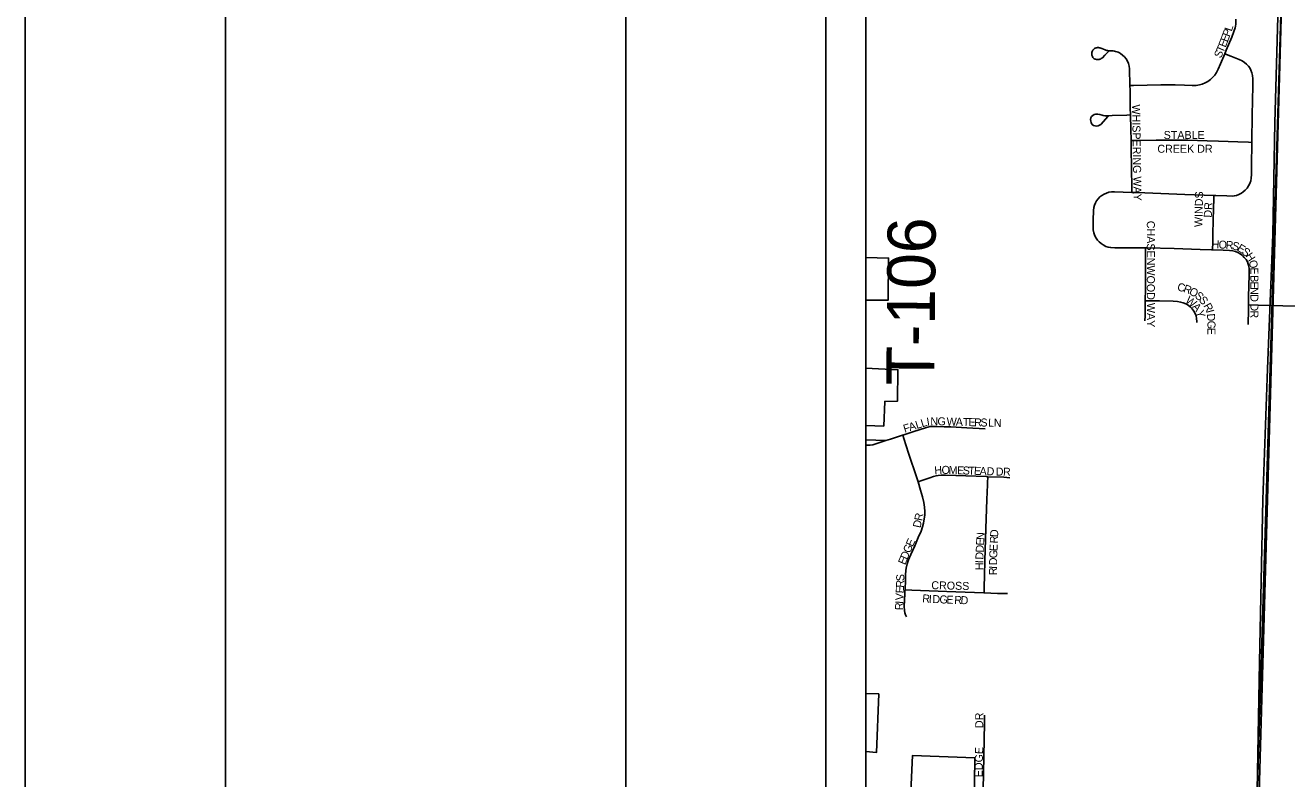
# Model space of a CAD drawing. Extents: x -5.6 to 34, y 0 to 22.
# Drawn here: x 0 to 3.152, y 14.869 to 16.752 of the extents above; entities that cross this region are included whole.
import ezdxf

# ---------------------------------------------------------------- set-up
doc = ezdxf.new("R2010")
doc.units = 0
for name, color, linetype in [('GM_X_City_Street', 7, 'Continuous'), ('GM_X_City_Street_Text', 7, 'Continuous'), ('GM_X_Corporation', 7, 'Continuous'), ('GM_X_Minor_River', 7, 'Continuous'), ('GM_X_Section', 7, 'Continuous'), ('GM_X_Township', 7, 'Continuous'), ('GM_X_Township_Road_Text', 7, 'Continuous'), ('SH_Border', 7, 'Continuous'), ('SH_Cut_Line', 7, 'Continuous'), ('SH_Data', 7, 'Continuous')]:
    doc.layers.add(name, color=color, linetype=linetype)

msp = doc.modelspace()

# ---------------------------------------------------------------- linework, layer by layer
at = {"layer": 'GM_X_City_Street'}
msp.add_line((2.1, 15.7156), (2.15, 15.7141), dxfattribs=at)
for points in [[(2.9966, 16.6798), (3.0005, 16.6891), (3.014, 16.7221), (3.0195, 16.7357), (3.0223, 16.7448), (3.0233, 16.7491), (3.0242, 16.7546), (3.0246, 16.7584), (3.0246, 16.7617), (3.0242, 16.7668)], [(2.7597, 16.6009), (2.7586, 16.6428), (2.7577, 16.6493), (2.7559, 16.6556), (2.7533, 16.6616), (2.7501, 16.6674), (2.7461, 16.6726), (2.7413, 16.6771), (2.736, 16.6809), (2.7333, 16.6824), (2.7302, 16.684), (2.7272, 16.6852), (2.724, 16.6862), (2.7209, 16.687), (2.7176, 16.6876), (2.7097, 16.6879), (2.706, 16.688), (2.7036, 16.6882), (2.7018, 16.6885), (2.6999, 16.689), (2.6977, 16.6899), (2.6896, 16.6932), (2.6847, 16.695), (2.6827, 16.6954), (2.6808, 16.6957), (2.679, 16.6957), (2.677, 16.6955), (2.675, 16.695), (2.6732, 16.6942), (2.6714, 16.6931), (2.6699, 16.692), (2.6684, 16.6907), (2.6671, 16.6894), (2.6661, 16.6878), (2.665, 16.6859), (2.6644, 16.6838), (2.6643, 16.6816), (2.6643, 16.6796), (2.6646, 16.6769), (2.6651, 16.6752), (2.6659, 16.6732), (2.6673, 16.671), (2.6691, 16.6691), (2.6708, 16.668), (2.6725, 16.6671), (2.6741, 16.6665), (2.6763, 16.666), (2.6783, 16.6657), (2.6802, 16.6659), (2.6825, 16.6661), (2.6845, 16.6666), (2.6861, 16.6671), (2.6881, 16.6682), (2.6894, 16.6691), (2.6909, 16.6704), (2.6971, 16.6767), (2.7078, 16.6872)], [(2.7597, 16.6009), (2.7689, 16.6012), (2.8024, 16.602), (2.8369, 16.6026), (2.8731, 16.6024), (2.8963, 16.6015), (2.9148, 16.6009), (2.9255, 16.6012), (2.9335, 16.6023), (2.9401, 16.6042), (2.9476, 16.6073), (2.9547, 16.6112), (2.9613, 16.616), (2.9662, 16.6206), (2.9715, 16.6268), (2.976, 16.6335), (2.9804, 16.6418), (2.9862, 16.6552), (2.9966, 16.6798)], [(3.0643, 16.459), (3.0652, 16.5299), (3.0659, 16.5601), (3.0668, 16.6034), (3.0668, 16.618), (3.066, 16.6261), (3.0645, 16.6327), (3.0621, 16.6391), (3.0589, 16.6451), (3.0556, 16.6496), (3.0509, 16.6545), (3.0456, 16.6587), (3.0398, 16.6623), (3.0325, 16.6658), (3.0117, 16.6739), (2.9966, 16.6798)], [(2.761, 16.5275), (2.7606, 16.5456), (2.76, 16.589), (2.7597, 16.6009)], [(2.7057, 16.524), (2.6873, 16.5039), (2.6841, 16.5017), (2.6804, 16.5003), (2.6765, 16.4998), (2.6726, 16.5002), (2.6689, 16.5015), (2.6657, 16.5039), (2.6641, 16.5059), (2.6629, 16.5083), (2.6618, 16.5121), (2.6616, 16.516), (2.6623, 16.5199), (2.6641, 16.5234), (2.6669, 16.5262), (2.6702, 16.5282), (2.674, 16.5295), (2.6793, 16.5298), (2.6844, 16.5287), (2.6903, 16.5268), (2.6932, 16.5261), (2.6974, 16.5255), (2.7022, 16.5253), (2.7156, 16.5259), (2.7518, 16.5272), (2.761, 16.5275)], [(2.7625, 16.4633), (2.7618, 16.4918), (2.761, 16.5275)], [(2.7625, 16.4633), (2.7812, 16.4637), (2.8252, 16.4645), (2.873, 16.4648), (2.9043, 16.4645), (2.9527, 16.4631), (2.9809, 16.4622), (3.0296, 16.4602), (3.056, 16.4593), (3.0643, 16.459)], [(2.7643, 16.3338), (2.7642, 16.346), (2.7637, 16.3946), (2.763, 16.4445), (2.7625, 16.4633)], [(2.9696, 16.3265), (2.9741, 16.3263), (3.0016, 16.3251), (3.0149, 16.3248), (3.0204, 16.3253), (3.0257, 16.3265), (3.0321, 16.3288), (3.0382, 16.3319), (3.0428, 16.335), (3.0478, 16.3395), (3.0524, 16.3446), (3.0562, 16.3503), (3.0592, 16.3564), (3.0614, 16.3629), (3.0628, 16.3695), (3.0636, 16.3789), (3.0636, 16.4065), (3.0642, 16.4525), (3.0643, 16.459)], [(2.7988, 16.1951), (2.7576, 16.1953), (2.7222, 16.1956), (2.7119, 16.1961), (2.7057, 16.1972), (2.6998, 16.1992), (2.6929, 16.2026), (2.6876, 16.206), (2.6828, 16.2101), (2.6786, 16.2148), (2.6751, 16.22), (2.6723, 16.2256), (2.6697, 16.2328), (2.6682, 16.2402), (2.6676, 16.2479), (2.6677, 16.2649), (2.6685, 16.2884), (2.6694, 16.2959), (2.6709, 16.3021), (2.6733, 16.3078), (2.6765, 16.3133), (2.6804, 16.3182), (2.6849, 16.3227), (2.6898, 16.3266), (2.6952, 16.3299), (2.701, 16.3324), (2.707, 16.3342), (2.7133, 16.3352), (2.7209, 16.3356), (2.7643, 16.3338)], [(2.7643, 16.3338), (2.7773, 16.3333), (2.8573, 16.3304), (2.8967, 16.329), (2.9696, 16.3265)], [(2.9658, 16.1904), (2.9666, 16.2094), (2.9671, 16.2287), (2.968, 16.2655), (2.9694, 16.3185), (2.9696, 16.3265)], [(2.7981, 16.0635), (2.7986, 16.0927), (2.7988, 16.1764), (2.7988, 16.1951)], [(2.9658, 16.1904), (2.9638, 16.1905), (2.9349, 16.1917), (2.8706, 16.1935), (2.801, 16.1951), (2.7988, 16.1951)], [(3.0561, 16.0534), (3.0562, 16.0733), (3.0574, 16.1284), (3.0575, 16.143), (3.0566, 16.1498), (3.0552, 16.1551), (3.0532, 16.1602), (3.0497, 16.1661), (3.0455, 16.1715), (3.0408, 16.1764), (3.0354, 16.1806), (3.0295, 16.184), (3.0231, 16.1865), (3.0165, 16.1881), (3.0084, 16.189), (2.9926, 16.1894), (2.9658, 16.1904)], [(2.797, 16.0128), (2.7974, 16.0259), (2.7981, 16.0635)], [(2.7981, 16.0635), (2.8034, 16.0634), (2.8135, 16.0632), (2.8338, 16.0627), (2.8678, 16.062), (2.8784, 16.0613), (2.8863, 16.06), (2.8929, 16.0583), (2.8991, 16.0557), (2.905, 16.0522), (2.9104, 16.048), (2.9151, 16.0431), (2.9192, 16.0376), (2.9224, 16.0317), (2.9248, 16.0253), (2.9263, 16.0186), (2.9268, 16.0118), (2.9267, 16.0091)], [(3.0552, 16.0037), (3.056, 16.0418), (3.0561, 16.0534)], [(3.0561, 16.0534), (3.0804, 16.0522), (3.142, 16.0502), (3.204, 16.0486), (3.2645, 16.0479), (3.2908, 16.0467), (3.3413, 16.0441), (3.3969, 16.0389), (3.4598, 16.0363), (3.5281, 16.0348), (3.5886, 16.0324), (3.598, 16.031), (3.6058, 16.0284), (3.6131, 16.0246), (3.6195, 16.0195), (3.625, 16.0134), (3.6302, 16.0055), (3.6336, 15.9981), (3.6357, 15.9902), (3.637, 15.9795), (3.6371, 15.9583), (3.636, 15.8939), (3.6356, 15.8747)], [(2.15, 15.7141), (2.1614, 15.7175), (2.1914, 15.7272), (2.1923, 15.7274)], [(2.1923, 15.7274), (2.2177, 15.7358), (2.2354, 15.7416), (2.249, 15.7459), (2.2545, 15.7477), (2.2605, 15.7488), (2.2639, 15.749), (2.2683, 15.7492), (2.2769, 15.7491), (2.2955, 15.7485), (2.3123, 15.748), (2.3522, 15.7462), (2.3982, 15.7437)], [(2.2304, 15.6106), (2.2272, 15.6207), (2.2064, 15.6826), (2.1948, 15.7194), (2.1923, 15.7274)], [(2.1, 15.7027), (2.1107, 15.7025), (2.1171, 15.7033), (2.15, 15.7141)], [(2.1979, 15.3413), (2.1991, 15.3662), (2.1994, 15.3784), (2.1999, 15.3897), (2.2005, 15.395), (2.203, 15.4058), (2.2065, 15.4165), (2.2123, 15.4298), (2.222, 15.4509), (2.2311, 15.4716), (2.2378, 15.4876), (2.2416, 15.4987), (2.2439, 15.5078), (2.2461, 15.5182), (2.2472, 15.5275), (2.2475, 15.5369), (2.2469, 15.5476), (2.2452, 15.5594), (2.2419, 15.5737), (2.2369, 15.5903), (2.2304, 15.6106)], [(2.2304, 15.6106), (2.2399, 15.6141), (2.2596, 15.6213), (2.2691, 15.6245), (2.2753, 15.626), (2.2806, 15.6268), (2.2881, 15.6273), (2.2991, 15.6275), (2.4003, 15.624), (2.4047, 15.6238)], [(2.3952, 15.3336), (2.3957, 15.348), (2.3966, 15.3767), (2.3975, 15.4134), (2.4001, 15.4946), (2.4024, 15.5666), (2.4036, 15.6032), (2.4039, 15.6084), (2.4047, 15.6238)], [(2.4047, 15.6238), (2.445, 15.6224), (2.4594, 15.6212)], [(2.2017, 15.2735), (2.1988, 15.2791), (2.1973, 15.2838), (2.1963, 15.2899), (2.1961, 15.2998), (2.1966, 15.3156), (2.1972, 15.3302), (2.1978, 15.3395), (2.1979, 15.3413)], [(2.1979, 15.3413), (2.2148, 15.3406), (2.258, 15.3389), (2.325, 15.3364), (2.3945, 15.3336), (2.3952, 15.3336)], [(2.3952, 15.3336), (2.4286, 15.3324), (2.447, 15.3322), (2.4535, 15.3317)], [(2.3933, 14.8413), (2.3964, 15.0088), (2.3964, 15.0258), (2.3962, 15.0284)]]:
    msp.add_lwpolyline(points, dxfattribs=at)
at = {"layer": 'GM_X_Corporation'}
for points in [[(3.2277, 20.9), (2.1, 20.9), (2.1, 18.226), (2.1688, 18.2231), (2.1708, 18.2767), (2.3867, 18.2751), (2.1, 17.7957), (2.1, 16.1715), (2.1566, 16.1698), (2.1557, 16.0644), (2.1, 16.0648), (2.1, 15.8951), (2.1803, 15.8911), (2.1794, 15.8126), (2.1472, 15.8117), (2.1446, 15.7502), (2.1, 15.7518), (2.1, 15.0823), (2.1322, 15.0813), (2.127, 14.9352), (2.1, 14.9372), (2.1, 14.8511)], [(2.2086, 14.7456), (2.2168, 14.9277), (2.3725, 14.9211), (2.3697, 14.7394)]]:
    msp.add_lwpolyline(points, dxfattribs=at)
at = {"layer": 'GM_X_Minor_River'}
msp.add_lwpolyline([(3.1727, 18.2606), (3.156, 17.9033), (3.1519, 17.6042), (3.1419, 17.1897), (3.1336, 16.8819), (3.1308, 16.8323), (3.1221, 16.5076), (3.1169, 16.2286), (3.1032, 15.8929), (3.0921, 15.5667), (3.0838, 15.1603), (3.0776, 14.8396), (3.0715, 14.6841), (2.7803, 14.6952), (2.5171, 14.7048), (2.3034, 14.7157)], dxfattribs=at)
at = {"layer": 'GM_X_Section'}
for points in [[(2.1, 16.9188), (2.1, 14.755), (3.0791, 14.7168), (3.1401, 16.8587)], [(3.1401, 16.8587), (5.2895, 16.8144), (5.2575, 14.6921), (3.0791, 14.7168)]]:
    msp.add_lwpolyline(points, close=True, dxfattribs=at)
at = {"layer": 'GM_X_Township'}
for points in [[(3.0636, 14.1), (8.9, 14.1), (8.9, 20.9), (2.1, 20.9), (2.1, 16.9108), (2.7242, 16.8707), (3.1388, 16.8616), (3.0745, 14.7121)], [(2.1, 16.9108), (2.1, 14.1), (3.0636, 14.1), (3.0745, 14.7121), (3.1388, 16.8616), (2.7242, 16.8707)]]:
    msp.add_lwpolyline(points, close=True, dxfattribs=at)
at = {"layer": 'SH_Border'}
for points in [[(0.5, 21.5), (1.5, 21.5), (1.5, 0.5), (0.5, 0.5)], [(1.5, 21.5), (33.5, 21.5), (33.5, 0.5), (1.5, 0.5)]]:
    msp.add_lwpolyline(points, close=True, dxfattribs=at)
at = {"layer": 'SH_Cut_Line'}
msp.add_lwpolyline([(0, 0), (34, 0), (34, 22), (0, 22)], close=True, dxfattribs=at)
at = {"layer": 'SH_Data'}
for p, q in [((2, 21), (2, 14)), ((2.1, 20.9), (2.1, 14.1))]:
    msp.add_line(p, q, dxfattribs=at)

# ---------------------------------------------------------------- texts
at = {"layer": 'GM_X_City_Street_Text'}
for s, rotation, p in [('P', 69.6038, (3.0087, 16.7212)), ('L', 71.1114, (3.0138, 16.735)), ('T', 66.6878, (2.9927, 16.6809)), ('E', 68.9942, (2.9986, 16.6947)), ('E', 69.6157, (3.0038, 16.708)), ('S', 65.3661, (2.9867, 16.6677)), ('WHISPERING WAY', 270.9239, (2.765, 16.5535)), ('STABLE', 0, (2.844, 16.4674)), ('CREEK DR', 0, (2.8282, 16.433)), ('WINDS', 88.7312, (2.9406, 16.2472)), ('DR', 86.989, (2.964, 16.2705)), ('CHASENWOOD WAY', 270, (2.802, 16.263)), ('H', 357.8579, (2.9635, 16.1946)), ('O', 357.3984, (2.981, 16.194)), ('R', 356.0874, (2.9985, 16.1932)), ('S', 346.7126, (3.0134, 16.1922)), ('E', 328.0149, (3.0256, 16.1897)), ('S', 323.3378, (3.0371, 16.1824)), ('H', 303.2658, (3.0472, 16.1754)), ('O', 284.6935, (3.0561, 16.1622)), ('E', 271.1747, (3.0604, 16.1464)), ('C', 347.3895, (2.8767, 16.0891)), ('B', 269.994, (3.0607, 16.1272)), ('E', 269.9956, (3.0607, 16.1113)), ('R', 339.5832, (2.8915, 16.0859)), ('W', 321.9599, (2.8965, 16.0609)), ('O', 331.7925, (2.9057, 16.0807)), ('S', 320.7087, (2.9203, 16.0729)), ('S', 310.5717, (2.9305, 16.0646)), ('N', 269.9928, (3.0607, 16.0973)), ('D', 269.9928, (3.0607, 16.0797)), ('A', 311.2579, (2.9138, 16.0475)), ('Y', 287.3775, (2.9243, 16.0361)), ('R', 299.2599, (2.9425, 16.0507)), ('D', 269.9928, (3.0607, 16.0568)), ('I', 284.8103, (2.9497, 16.0381)), ('D', 275.143, (2.9518, 16.0305)), ('G', 270, (2.9534, 16.0135)), ('R', 269.994, (3.0607, 16.0392)), ('E', 269.9956, (2.9534, 15.9959)), ('A', 17.2949, (2.2104, 15.7375)), ('L', 17.3134, (2.2272, 15.7428)), ('L', 16.8798, (2.2406, 15.7469)), ('I', 8.9522, (2.2534, 15.7509)), ('N', 0.5902, (2.2613, 15.7522)), ('G', 358.4259, (2.2787, 15.7524)), ('W', 358.4215, (2.3016, 15.7517)), ('A', 358.4259, (2.3244, 15.7511)), ('T', 358.4363, (2.342, 15.7506)), ('E', 358.4149, (2.3561, 15.7502)), ('R', 358.4139, (2.3702, 15.7498)), ('S', 358.4114, (2.386, 15.7494)), ('L', 358.4363, (2.4054, 15.7489)), ('N', 358.404, (2.4194, 15.7485)), ('F', 17.3116, (2.197, 15.7333)), ('H', 5.0559, (2.272, 15.6294)), ('O', 358.8416, (2.289, 15.631)), ('M', 358.16, (2.3065, 15.6306)), ('E', 358.1461, (2.3276, 15.6299)), ('S', 358.1691, (2.3417, 15.6295)), ('T', 358.1418, (2.3558, 15.629)), ('E', 358.1599, (2.3698, 15.6286)), ('A', 358.1575, (2.3839, 15.6281)), ('D', 358.1637, (2.4015, 15.6276)), ('D', 358.3377, (2.4244, 15.6268)), ('R', 359.5072, (2.4425, 15.6263)), ('D', 78.2914, (2.2366, 15.4947)), ('R', 79.1801, (2.2403, 15.5123)), ('N', 87.1239, (2.3958, 15.4654)), ('R', 87.4493, (2.4296, 15.4567)), ('D', 87.4708, (2.4303, 15.4725)), ('G', 67.3667, (2.2103, 15.4313)), ('E', 65.4882, (2.217, 15.4474)), ('D', 87.1354, (2.3942, 15.4338)), ('E', 87.1308, (2.3951, 15.4514)), ('E', 87.5401, (2.4287, 15.4374)), ('E', 67.3717, (2.1981, 15.4021)), ('D', 67.3667, (2.2035, 15.4151)), ('I', 88.6881, (2.3932, 15.4075)), ('D', 87.4421, (2.3934, 15.4162)), ('D', 88.6449, (2.4277, 15.4023)), ('G', 88.0108, (2.4281, 15.4198)), ('H', 89.8251, (2.3932, 15.3901)), ('I', 89.3445, (2.4276, 15.3935)), ('R', 89.9271, (2.4276, 15.3777)), ('E', 87.4036, (2.1945, 15.3321)), ('R', 87.4393, (2.1951, 15.3462)), ('S', 89.1163, (2.1958, 15.3627)), ('CROSS', 358.6987, (2.2633, 15.3428)), ('V', 87.4258, (2.1937, 15.3146)), ('R', 354.4779, (2.2402, 15.3104)), ('I', 356.7546, (2.2568, 15.3088)), ('D', 357.4822, (2.2659, 15.3083)), ('G', 357.9549, (2.2836, 15.3075)), ('E', 357.9968, (2.3012, 15.3069)), ('R', 357.9841, (2.3206, 15.3062)), ('D', 357.9671, (2.3364, 15.3056)), ('R', 87.425, (2.1926, 15.2899)), ('I', 87.4193, (2.1933, 15.3058)), ('DR', 90, (2.3932, 14.9958)), ('EDGE', 88.7817, (2.3914, 14.8727))]:
    msp.add_text(s, height=0.02, rotation=rotation, dxfattribs=at).set_placement(p)
at = {"layer": 'GM_X_Township_Road_Text'}
msp.add_text('T-106', height=0.12, rotation=89.4627, dxfattribs=at).set_placement((2.2708, 15.8517))

doc.saveas('drawing.dxf')
